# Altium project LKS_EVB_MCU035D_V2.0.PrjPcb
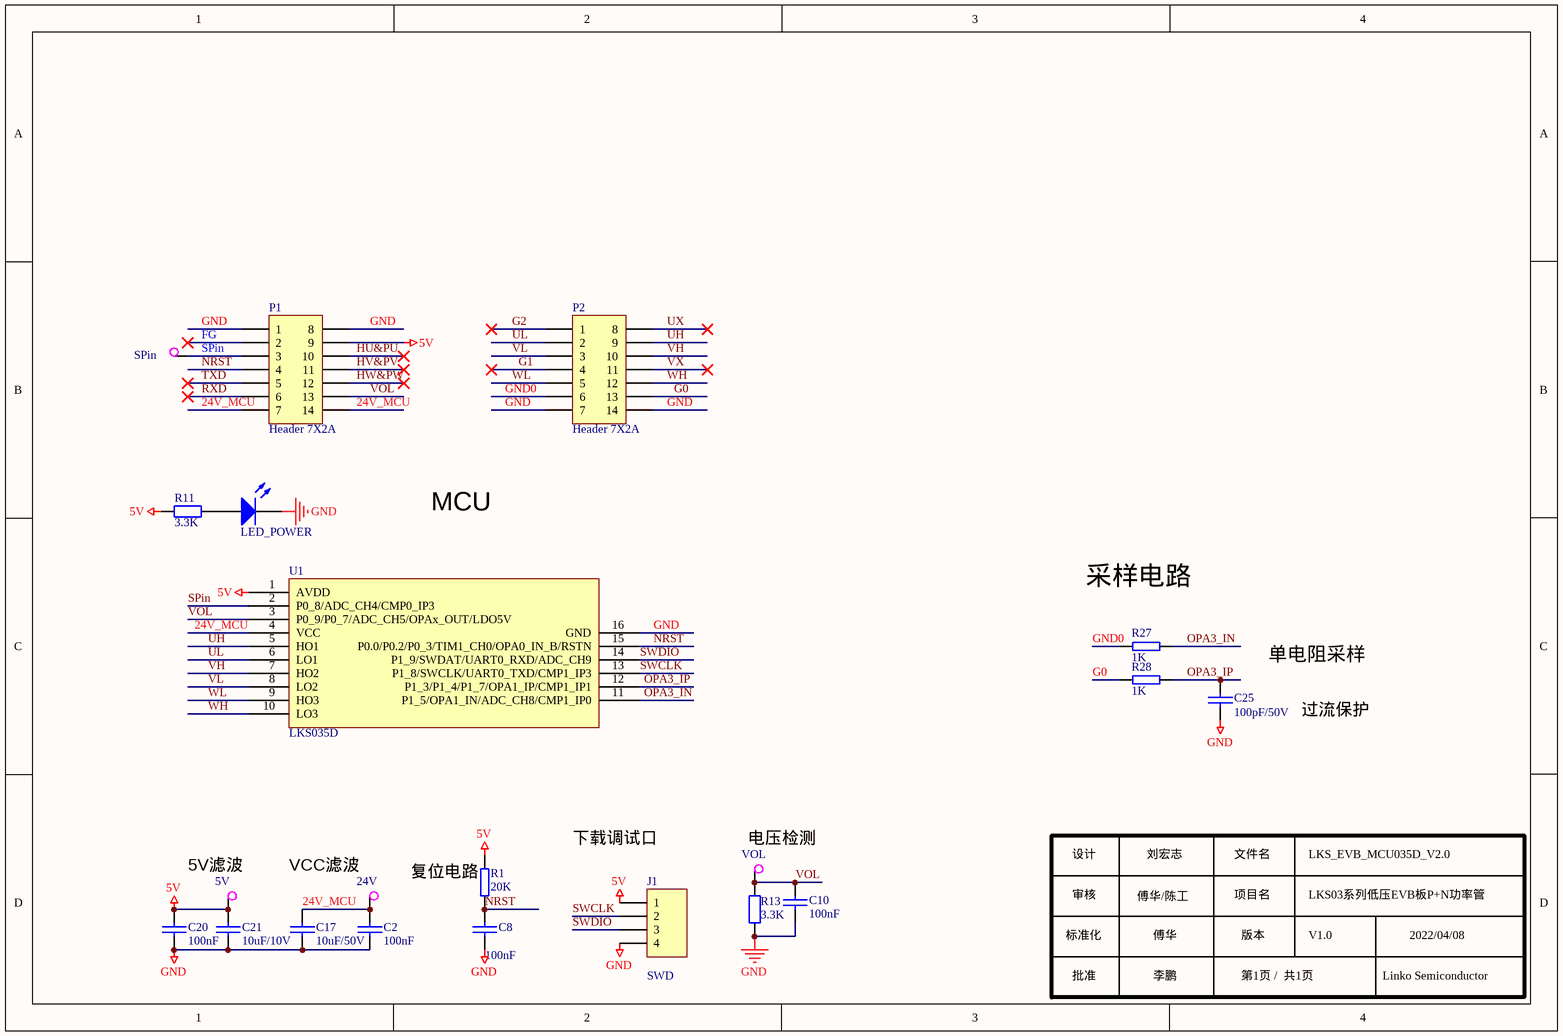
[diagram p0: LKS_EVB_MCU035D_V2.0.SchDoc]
1 sheet, 21 parts. Net scope: global (net labels, ports and power ports of the same name join across sheets).
Board file: LKS_EVB_MCU035D_V2.0.PcbDoc

## Sheet LKS_EVB_MCU035D_V2.0.SchDoc: LKS087_DEMO_V2.0_200109
size A4; Revision: V1.0; SheetNumber: 1; SheetTotal: 1

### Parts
5V  TestP  [TP-40]  (value not drawn)
24V  TestP  [TP-40]  (value not drawn)
C2  100nF  [0805C]
C8  100nF  [0805C]
C10  100nF  [0805C]
C17  10uF/50V  [1206]
C20  100nF  [0805C]
C21  10uF/10V  [0805C]
C25  100pF/50V  [0805C]
J1  SWD  [SIP4-2.5]
LED_POWER  (no value)  [0805D]
P1  Header 7X2A  [HDR2X7_CEN]
P2  Header 7X2A  [HDR2X7_CEN]
R1  20K  [0805R]
R11  3.3K  [0603R]
R13  3.3K  [0805R]
R27  1K  [0805R]
R28  1K  [0805R]
SPin  TestP  [TP-40]  (value not drawn)
U1  LKS035D  [SOP-16]
VOL  TestP  [TP-40]  (value not drawn)

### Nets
5V: 5V.1 C20.1 C21.1 J1.1 P1.9 R1.1 R11.2 U1.1(AVDD)
GND: C2.2 C8.2 C10.2 C17.1 C20.2 C21.2 C25.1 J1.4 LED_POWER.2(K) P1.1 P1.8 P2.7 P2.14 R13.2 U1.16(GND)
24V_MCU: 24V.1 C2.1 C17.2 P1.7 P1.14 U1.4(VCC)
FG: P1.2
G0: P2.13 R28.2
G1: P2.4
G2: P2.1
GND0: P2.6 R27.2
HU&PU: P1.10
HV&PV: P1.11
HW&PW: P1.12
NRST: C8.1 P1.4 R1.2 U1.15(P0.0/P0.2/P0_3/TIM1_CH0/OPA0_IN_B/RSTN)
OPA3_IN: R27.1 U1.11(P1_5/OPA1_IN/ADC_CH8/CMP1_IP0)
OPA3_IP: C25.2 R28.1 U1.12(P1_3/P1_4/P1_7/OPA1_IP/CMP1_IP1)
RXD: P1.6
SPin: P1.3 SPin.1 U1.2(P0_8/ADC_CH4/CMP0_IP3)
SWCLK: J1.2 U1.13(P1_8/SWCLK/UART0_TXD/CMP1_IP3)
SWDIO: J1.3 U1.14(P1_9/SWDAT/UART0_RXD/ADC_CH9)
TXD: P1.5
UH: P2.9 U1.5(HO1)
UL: P2.2 U1.6(LO1)
UX: P2.8
VH: P2.10 U1.7(HO2)
VL: P2.3 U1.8(LO2)
VOL: C10.1 P1.13 R13.1 U1.3(P0_9/P0_7/ADC_CH5/OPAx_OUT/LDO5V) VOL.1
VX: P2.11
WH: P2.12 U1.10(LO3)
WL: P2.5 U1.9(HO3)
NetLED_POWER_1: LED_POWER.1(A) R11.1

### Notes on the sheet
- MCU
- 采样电路
- 过流保护
- (near 5V) 5V滤波
- VCC滤波
- 复位电路
- 设计
- 审核
- 傅华/陈工
- 刘宏志
- 文件名
- 项目名
- LKS_EVB_MCU035D_V2.0
- LKS03系列低压EVB板P+N功率管
- 标准化
- 批准
- 傅华
- 李鹏
- 版本
- 第1页 /  共1页
- V1.0
- Linko Semiconductor
- 2022/04/08
- Labels drawn without touching a wire or pin: 下载调试口, 单电阻采样, 电压检测

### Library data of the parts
C2 C10 C17 = CAP: Capacitor
C8 C20 C21 C25 = C: Capacitor
J1 = Header 4: Header, 4-Pin
LED_POWER = LED2: Typical RED, GREEN, YELLOW, AMBER GaAs LED
P1 P2 = Header 7X2A: Header, 7-Pin, Dual row
R1 R27 R28 = RES2-1
R11 R13 = Res2: Resistor
U1 = LKS32MC035DL6S8: CHIP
